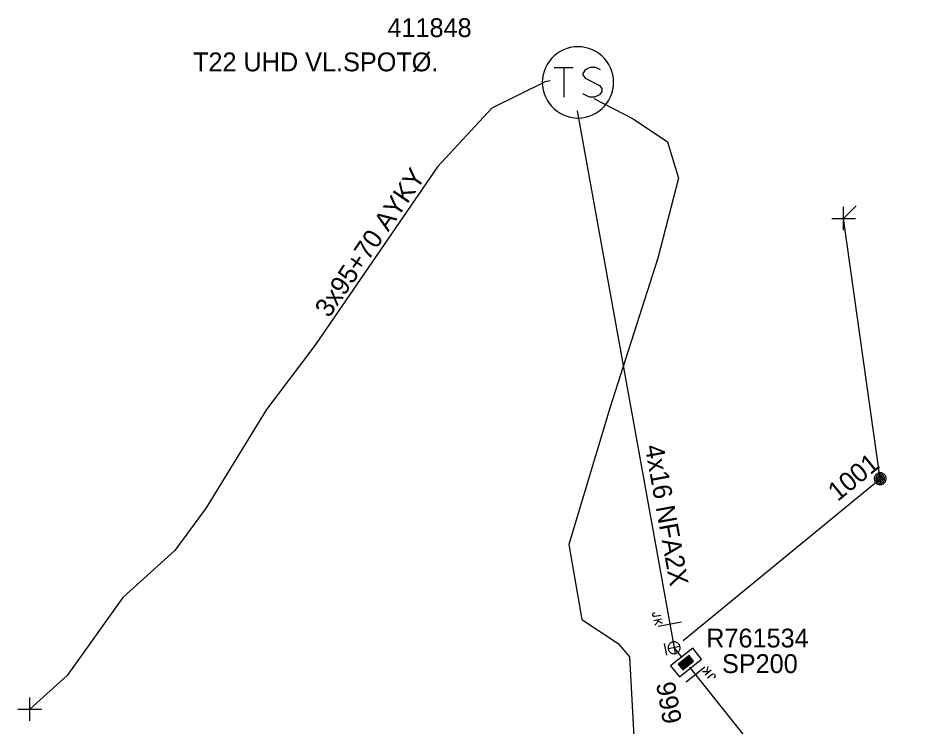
# Model space of a CAD drawing. Extents: x -540247 to -537390, y -1183890 to -1180355.
# Drawn here: x -537506.26 to -537458.71, y -1180635 to -1180597.48 of the extents above; entities that cross this region are included whole.
import ezdxf

# ---------------------------------------------------------------- set-up
doc = ezdxf.new("R2010")
doc.units = 0
for name, color, linetype in [('Vrstva 1', 7, 'Continuous'), ('Vrstva 13', 7, 'Continuous'), ('Vrstva 14', 7, 'Continuous'), ('Vrstva 15', 7, 'Continuous'), ('Vrstva 18', 7, 'Continuous'), ('Vrstva 2', 7, 'Continuous'), ('Vrstva 25', 7, 'Continuous'), ('Vrstva 26', 7, 'Continuous'), ('Vrstva 27', 7, 'Continuous'), ('Vrstva 28', 7, 'Continuous'), ('Vrstva 29', 7, 'Continuous'), ('Vrstva 30', 7, 'Continuous'), ('Vrstva 34', 7, 'Continuous'), ('Vrstva 50', 7, 'Continuous'), ('Vrstva 51', 7, 'Continuous'), ('Vrstva 52', 7, 'Continuous'), ('Vrstva 54', 7, 'Continuous'), ('Vrstva 6', 7, 'Continuous'), ('Vrstva 8', 7, 'Continuous')]:
    doc.layers.add(name, color=color, linetype=linetype)

# ---------------------------------------------------------------- blocks, each defined once
blk = doc.blocks.new('NN840')
at = {"layer": 'Vrstva 15'}
for points in [[(0.003, 0.619), (0.003, -0.631)], [(-0.538, -0.385), (-0.538, -0.71)], [(-0.332, -0.385), (-0.332, -0.798)], [(-0.332, -0.641), (-0.125, -0.385)], [(-0.745, -0.71), (-0.745, -0.66)], [(-0.73, -0.764), (-0.745, -0.71)], [(-0.657, -0.798), (-0.73, -0.764)], [(-0.627, -0.798), (-0.657, -0.798)], [(-0.558, -0.764), (-0.627, -0.798)], [(-0.538, -0.71), (-0.558, -0.764)], [(-0.263, -0.557), (-0.091, -0.798)]]:
    blk.add_lwpolyline(points, dxfattribs=at)
blk = doc.blocks.new('NN460')
at = {"layer": 'Vrstva 2'}
for points in [[(0.628, 0), (0.624, 0.066), (0.614, 0.132), (0.597, 0.195), (0.573, 0.257), (0.543, 0.315), (0.507, 0.371), (0.466, 0.422), (0.419, 0.468), (0.368, 0.51), (0.312, 0.546), (0.254, 0.576), (0.192, 0.6), (0.129, 0.617), (0.063, 0.627), (-0.003, 0.631), (-0.068, 0.627), (-0.133, 0.617), (-0.197, 0.6), (-0.259, 0.576), (-0.317, 0.546), (-0.373, 0.51), (-0.424, 0.468), (-0.471, 0.422), (-0.512, 0.371), (-0.548, 0.315), (-0.578, 0.257), (-0.602, 0.195), (-0.619, 0.132), (-0.629, 0.066), (-0.632, 0), (-0.629, -0.065), (-0.619, -0.131), (-0.602, -0.194), (-0.578, -0.256), (-0.548, -0.315), (-0.512, -0.37), (-0.471, -0.421), (-0.424, -0.468), (-0.373, -0.509), (-0.317, -0.545), (-0.259, -0.575), (-0.197, -0.599), (-0.133, -0.616), (-0.068, -0.626), (-0.003, -0.63), (0.063, -0.626), (0.129, -0.616), (0.192, -0.599), (0.254, -0.575), (0.313, -0.545), (0.368, -0.509), (0.419, -0.468), (0.466, -0.421), (0.507, -0.37), (0.543, -0.315), (0.573, -0.256), (0.597, -0.194), (0.614, -0.131), (0.624, -0.065), (0.628, 0)], [(0.47, 0), (0.467, 0.05), (0.46, 0.099), (0.447, 0.147), (0.429, 0.193), (0.407, 0.237), (0.38, 0.278), (0.349, 0.317), (0.314, 0.352), (0.275, 0.383), (0.234, 0.41), (0.19, 0.432), (0.144, 0.45), (0.096, 0.463), (0.047, 0.47), (-0.003, 0.473), (-0.052, 0.47), (-0.1, 0.463), (-0.148, 0.45), (-0.194, 0.432), (-0.239, 0.41), (-0.28, 0.383), (-0.319, 0.352), (-0.353, 0.317), (-0.385, 0.278), (-0.411, 0.237), (-0.434, 0.193), (-0.452, 0.147), (-0.465, 0.099), (-0.472, 0.05), (-0.475, 0), (-0.472, -0.049), (-0.465, -0.098), (-0.452, -0.146), (-0.434, -0.192), (-0.411, -0.236), (-0.385, -0.277), (-0.353, -0.316), (-0.318, -0.351), (-0.28, -0.382), (-0.239, -0.409), (-0.194, -0.431), (-0.148, -0.449), (-0.1, -0.462), (-0.052, -0.469), (-0.003, -0.472), (0.047, -0.469), (0.096, -0.462), (0.144, -0.449), (0.19, -0.431), (0.234, -0.409), (0.275, -0.382), (0.314, -0.351), (0.349, -0.316), (0.38, -0.277), (0.407, -0.236), (0.429, -0.192), (0.447, -0.146), (0.46, -0.098), (0.467, -0.049), (0.47, 0)], [(0.313, 0), (0.311, 0.033), (0.306, 0.066), (0.297, 0.098), (0.285, 0.129), (0.27, 0.158), (0.252, 0.186), (0.232, 0.211), (0.208, 0.234), (0.183, 0.255), (0.155, 0.273), (0.126, 0.288), (0.095, 0.3), (0.063, 0.309), (0.03, 0.314), (-0.003, 0.315), (-0.035, 0.314), (-0.068, 0.309), (-0.1, 0.3), (-0.13, 0.288), (-0.16, 0.273), (-0.187, 0.255), (-0.213, 0.234), (-0.237, 0.211), (-0.257, 0.186), (-0.275, 0.158), (-0.29, 0.129), (-0.302, 0.098), (-0.31, 0.066), (-0.316, 0.033), (-0.317, 0), (-0.316, -0.033), (-0.31, -0.065), (-0.302, -0.097), (-0.29, -0.128), (-0.275, -0.157), (-0.257, -0.185), (-0.237, -0.21), (-0.213, -0.234), (-0.187, -0.254), (-0.16, -0.272), (-0.13, -0.287), (-0.1, -0.299), (-0.068, -0.308), (-0.035, -0.313), (-0.003, -0.315), (0.03, -0.313), (0.063, -0.308), (0.095, -0.299), (0.126, -0.287), (0.155, -0.272), (0.183, -0.254), (0.208, -0.234), (0.232, -0.21), (0.252, -0.185), (0.27, -0.157), (0.285, -0.128), (0.297, -0.097), (0.306, -0.065), (0.311, -0.032), (0.313, 0)], [(0.155, 0), (0.154, 0.017), (0.152, 0.033), (0.147, 0.049), (0.142, 0.064), (0.134, 0.079), (0.125, 0.093), (0.115, 0.106), (0.103, 0.118), (0.09, 0.128), (0.076, 0.137), (0.062, 0.144), (0.046, 0.15), (0.03, 0.154), (0.014, 0.157), (-0.003, 0.158), (-0.019, 0.157), (-0.035, 0.154), (-0.051, 0.15), (-0.066, 0.144), (-0.081, 0.137), (-0.095, 0.128), (-0.108, 0.118), (-0.119, 0.106), (-0.13, 0.093), (-0.139, 0.079), (-0.146, 0.064), (-0.152, 0.049), (-0.156, 0.033), (-0.159, 0.017), (-0.16, 0), (-0.159, -0.016), (-0.156, -0.032), (-0.152, -0.048), (-0.146, -0.064), (-0.139, -0.078), (-0.13, -0.092), (-0.119, -0.105), (-0.108, -0.117), (-0.095, -0.127), (-0.081, -0.136), (-0.066, -0.143), (-0.051, -0.149), (-0.035, -0.153), (-0.019, -0.156), (-0.003, -0.157), (0.014, -0.156), (0.03, -0.153), (0.046, -0.149), (0.062, -0.143), (0.076, -0.136), (0.09, -0.127), (0.103, -0.117), (0.115, -0.105), (0.125, -0.092), (0.134, -0.078), (0.142, -0.064), (0.147, -0.048), (0.152, -0.032), (0.154, -0.016), (0.155, 0)]]:
    blk.add_lwpolyline(points, dxfattribs=at)
blk = doc.blocks.new('NN800')
at = {"layer": 'Vrstva 1'}
for points in [[(-0.442, 0.442), (0.442, -0.442)], [(-0.442, -0.442), (0.442, 0.442)]]:
    blk.add_lwpolyline(points, dxfattribs=at)
blk = doc.blocks.new('NN620')
at = {"layer": 'Vrstva 8'}
for points in [[(0.752, 0.004), (-0.748, 0.004)], [(-0.748, 0.004), (-0.748, -0.746)], [(0.752, -0.746), (0.752, 0.004)], [(0.368, -0.18), (-0.376, -0.18)], [(-0.376, -0.18), (-0.376, -0.558)], [(0.321, -0.227), (-0.329, -0.227)], [(-0.329, -0.227), (-0.329, -0.51)], [(0.274, -0.274), (-0.281, -0.274)], [(-0.281, -0.274), (-0.281, -0.463)], [(-0.281, -0.463), (0.274, -0.463)], [(0.227, -0.321), (-0.234, -0.321)], [(-0.234, -0.321), (-0.234, -0.416)], [(-0.234, -0.416), (0.227, -0.416)], [(-0.193, -0.369), (0.185, -0.369)], [(0.227, -0.416), (0.227, -0.321)], [(0.274, -0.463), (0.274, -0.274)], [(0.321, -0.51), (0.321, -0.227)], [(0.368, -0.558), (0.368, -0.18)], [(-0.748, -0.746), (0.752, -0.746)], [(-0.376, -0.558), (0.368, -0.558)], [(-0.329, -0.51), (0.321, -0.51)]]:
    blk.add_lwpolyline(points, dxfattribs=at)
blk = doc.blocks.new('NN610')
at = {"layer": 'Vrstva 6'}
for points in [[(1.883, -0.001), (1.872, 0.196), (1.841, 0.392), (1.79, 0.583), (1.718, 0.768), (1.629, 0.943), (1.521, 1.109), (1.397, 1.263), (1.257, 1.403), (1.103, 1.527), (0.937, 1.635), (0.761, 1.725), (0.577, 1.796), (0.19, 1.878), (0.19, 1.878), (-0.007, 1.889), (-0.205, 1.878), (-0.401, 1.847), (-0.591, 1.796), (-0.777, 1.725), (-0.952, 1.635), (-1.118, 1.527), (-1.272, 1.403), (-1.412, 1.263), (-1.536, 1.109), (-1.644, 0.943), (-1.734, 0.768), (-1.805, 0.583), (-1.856, 0.392), (-1.887, 0.196), (-1.898, -0.001), (-1.887, -0.199), (-1.856, -0.395), (-1.805, -0.585), (-1.734, -0.77), (-1.644, -0.946), (-1.536, -1.112), (-1.411, -1.266), (-1.272, -1.405), (-1.118, -1.53), (-0.952, -1.638), (-0.776, -1.728), (-0.591, -1.799), (-0.401, -1.85), (-0.205, -1.881), (-0.007, -1.892), (0.19, -1.881), (0.385, -1.85), (0.577, -1.799), (0.761, -1.728), (0.937, -1.638), (1.103, -1.53), (1.257, -1.405), (1.397, -1.266), (1.521, -1.112), (1.629, -0.946), (1.718, -0.77), (1.79, -0.585), (1.841, -0.395), (1.872, -0.199), (1.883, -0.001)], [(-1.269, 0.782), (-0.261, 0.782)], [(-0.765, 0.782), (-0.765, -0.792)], [(1.188, 0.656), (0.936, 0.782), (0.621, 0.782), (0.369, 0.656), (0.243, 0.468), (0.243, 0.404), (0.369, 0.216), (1.125, -0.162), (1.251, -0.32), (1.251, -0.478), (1.125, -0.666), (0.873, -0.792), (0.621, -0.792), (0.495, -0.73), (0.243, -0.604)]]:
    blk.add_lwpolyline(points, dxfattribs=at)
blk = doc.blocks.new('NN410')
at = {"layer": 'Vrstva 2'}
for points in [[(0.005, 0.632), (-0.061, 0.628), (-0.126, 0.618), (-0.19, 0.601), (-0.251, 0.577), (-0.31, 0.547), (-0.365, 0.511), (-0.416, 0.47), (-0.463, 0.423), (-0.505, 0.372), (-0.541, 0.317), (-0.57, 0.258), (-0.594, 0.196), (-0.611, 0.133), (-0.621, 0.068), (-0.625, 0.002), (-0.621, -0.064), (-0.611, -0.129), (-0.594, -0.193), (-0.57, -0.254), (-0.541, -0.313), (-0.505, -0.368), (-0.463, -0.42), (-0.416, -0.466), (-0.365, -0.508), (-0.31, -0.544), (-0.251, -0.574), (-0.19, -0.597), (-0.126, -0.614), (-0.061, -0.625), (0.005, -0.628), (0.071, -0.625), (0.136, -0.614), (0.2, -0.597), (0.261, -0.574), (0.32, -0.544), (0.375, -0.508), (0.427, -0.466), (0.473, -0.42), (0.515, -0.368), (0.55, -0.313), (0.581, -0.254), (0.604, -0.193), (0.621, -0.129), (0.632, -0.064), (0.635, 0.002), (0.632, 0.068), (0.621, 0.133), (0.604, 0.196), (0.58, 0.258), (0.55, 0.317), (0.515, 0.372), (0.473, 0.423), (0.427, 0.47), (0.375, 0.511), (0.32, 0.547), (0.261, 0.577), (0.2, 0.601), (0.136, 0.618), (0.071, 0.628), (0.005, 0.632)], [(0.004, -0.631), (0.004, 0.629)], [(0.958, -0.631), (0.958, 0.629)], [(-0.626, -0.001), (0.633, -0.001)]]:
    blk.add_lwpolyline(points, dxfattribs=at)
blk = doc.blocks.new('NN510')
at = {"layer": 'Vrstva 2'}
blk.add_lwpolyline([(0.001, 0.002), (0.001, 0.939)], dxfattribs=at)

msp = doc.modelspace()

# ---------------------------------------------------------------- linework, layer by layer
at = {"layer": 'Vrstva 50'}
msp.add_lwpolyline([(-537476.621, -1180602.404), (-537471.479, -1180630.847), (-537471.081, -1180631.347)], dxfattribs=at)
at = {"layer": 'Vrstva 52'}
for points in [[(-537478.043, -1180600.816), (-537478.316, -1180600.862), (-537481.145, -1180602.264), (-537484.029, -1180605.364), (-537490.514, -1180614.834), (-537493.09, -1180618.224), (-537496.285, -1180623.429), (-537497.937, -1180625.69), (-537500.696, -1180628.194), (-537503.652, -1180632.327), (-537505.631, -1180634.101)], [(-537475.729, -1180601.74), (-537473.65, -1180602.83), (-537471.84, -1180604.05), (-537471.24, -1180605.97), (-537472.34, -1180610.21), (-537474.88, -1180618.16), (-537477.06, -1180625.37), (-537476.38, -1180629.35), (-537474.45, -1180630.62), (-537473.84, -1180631.33), (-537473.3, -1180641.39), (-537472.18, -1180654.43), (-537471.67, -1180655.81), (-537470.45, -1180660.74), (-537469.79, -1180662.87), (-537469.862, -1180662.98)], [(-537470.662, -1180631.873), (-537458.712, -1180646.885)]]:
    msp.add_lwpolyline(points, dxfattribs=at)
at = {"layer": 'Vrstva 54'}
msp.add_lwpolyline([(-537471.01, -1180630.462), (-537460.558, -1180621.891), (-537462.5, -1180608.103)], dxfattribs=at)

# ---------------------------------------------------------------- block references
at = {"layer": 'Vrstva 13', "rotation": -45.009741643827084}
msp.add_blockref('NN510', (-537462.501, -1180608.103), dxfattribs=at)
at = {"layer": 'Vrstva 13', "yscale": 0.5000000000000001}
for name, p, xscale, rotation in [('NN460', (-537460.558, -1180621.892), 0.5000000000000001, 39.35419993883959), ('NN410', (-537471.479, -1180630.847), 0.49999999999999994, -169.6218472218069)]:
    msp.add_blockref(name, p, dxfattribs=dict(at, xscale=xscale, rotation=rotation))
at = {"layer": 'Vrstva 18'}
for p, rotation in [((-537471.705, -1180629.6), -79.75271346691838), ((-537470.352, -1180632.263), 128.521460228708)]:
    msp.add_blockref('NN840', p, dxfattribs=dict(at, rotation=rotation))
at = {"layer": 'Vrstva 25', "rotation": 0.004327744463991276}
msp.add_blockref('NN610', (-537476.569, -1180600.89), dxfattribs=at)
at = {"layer": 'Vrstva 28', "rotation": 38.521460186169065}
msp.add_blockref('NN620', (-537471.081, -1180631.347), dxfattribs=at)
at = {"layer": 'Vrstva 34', "rotation": 45}
for p in [(-537462.5, -1180608.103), (-537505.631, -1180634.101)]:
    msp.add_blockref('NN800', p, dxfattribs=at)

# ---------------------------------------------------------------- texts
at = {"layer": 'Vrstva 14'}
for s, rotation, p in [('1001', 39.354, (-537462.814, -1180623.131)), ('999', 280.247, (-537472.444, -1180632.753))]:
    msp.add_text(s, height=1, rotation=rotation, dxfattribs=at).set_placement(p)
at = {"layer": 'Vrstva 26'}
msp.add_text('411848', height=1, dxfattribs=at).set_placement((-537486.674, -1180598.493))
at = {"layer": 'Vrstva 27'}
msp.add_text('T22 UHD VL.SPOTØ.', height=1, dxfattribs=at).set_placement((-537496.977, -1180600.307))
at = {"layer": 'Vrstva 29'}
msp.add_text('R761534', height=1, dxfattribs=at).set_placement((-537469.779, -1180630.835))
at = {"layer": 'Vrstva 30'}
msp.add_text('SP200', height=1, dxfattribs=at).set_placement((-537468.943, -1180632.19))
at = {"layer": 'Vrstva 51'}
msp.add_text('4x16 NFA2X', height=1, rotation=280.247, dxfattribs=at).set_placement((-537473.039, -1180620.174))
at = {"layer": 'Vrstva 54'}
msp.add_text('3x95+70 AYKY', height=1, rotation=55.597, dxfattribs=at).set_placement((-537489.767, -1180613.411))

doc.saveas('drawing.dxf')
